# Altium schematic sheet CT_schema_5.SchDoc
size 284 x 243 mm
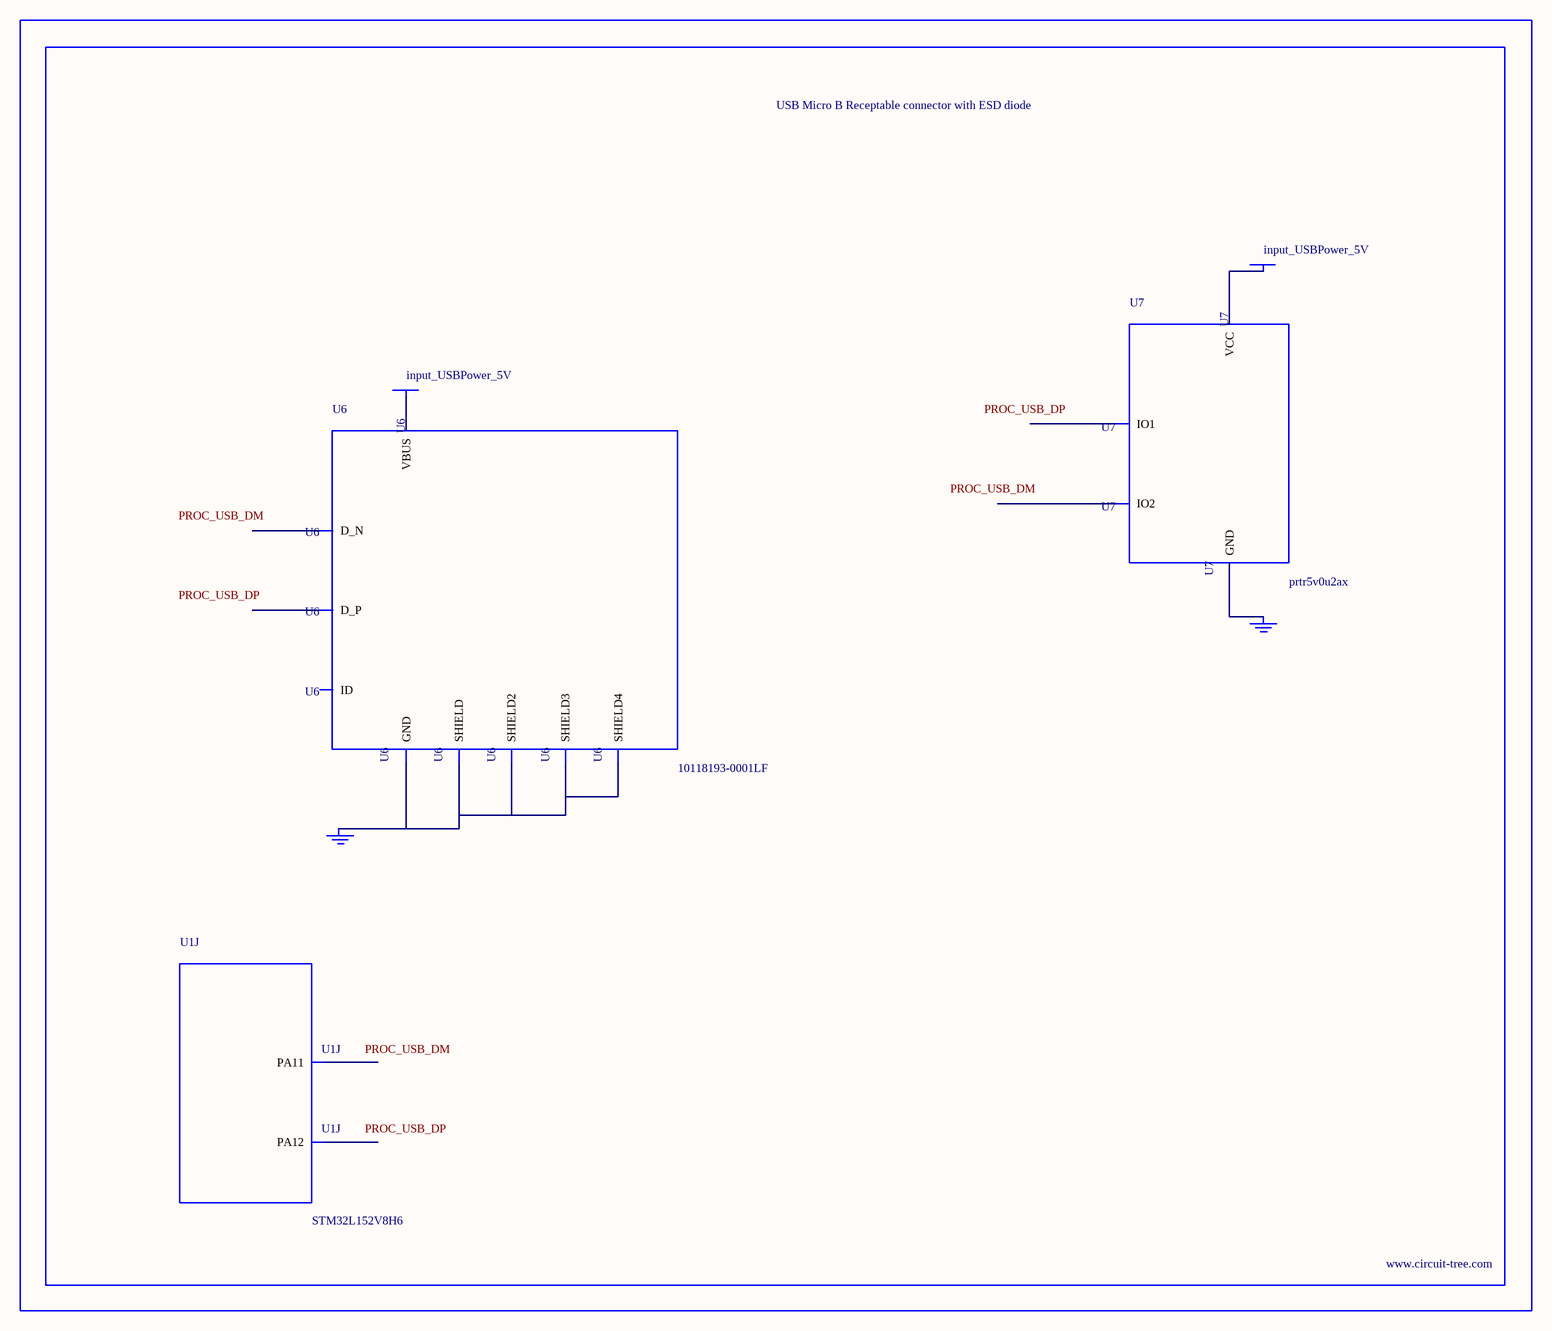
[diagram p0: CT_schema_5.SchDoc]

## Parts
BORDER4  (no value)
GND_INSTANCE_4_0  (no value)
GND_INSTANCE_4_1  (no value)
POWER_INSTANCE_4_0  input_USBPower_5V
POWER_INSTANCE_4_1  input_USBPower_5V
U1  STM32L152V8H6  [UFBGA100]  (part J of 10)
U6  10118193-0001LF  [FCI_10118193-0001LF]
U7  prtr5v0u2ax  [SOT143B]

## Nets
NetGND_INSTANCE_4_0_0: GND_INSTANCE_4_0.0(GND) U6.5(GND) U6.6(SHIELD) U6.7(SHIELD2) U6.8(SHIELD3) U6.9(SHIELD4)
NetGND_INSTANCE_4_1_0: GND_INSTANCE_4_1.0(GND) U7.1(GND)
NetPOWER_INSTANCE_4_0_0: POWER_INSTANCE_4_0.0(PWR) U6.1(VBUS)
NetPOWER_INSTANCE_4_1_0: POWER_INSTANCE_4_1.0(PWR) U7.4(VCC)

Not connected (* = marked no-connect by the designer): U1 A12(PA12) B12(PA11); U6 2(D_N) 3(D_P) 4(ID); U7 2(IO1) 3(IO2)

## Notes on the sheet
- Labels drawn without touching a wire or pin: PROC_USB_DM, PROC_USB_DP

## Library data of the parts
BORDER4 = BORDER_PAGE4
GND_INSTANCE_4_0 GND_INSTANCE_4_1 = GND
POWER_INSTANCE_4_0 POWER_INSTANCE_4_1 = PWR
